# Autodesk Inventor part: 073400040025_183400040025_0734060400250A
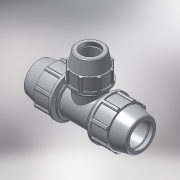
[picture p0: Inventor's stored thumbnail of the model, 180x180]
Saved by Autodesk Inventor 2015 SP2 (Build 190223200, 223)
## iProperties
Created: 2017-02
Part Number: 073400040025_183400040025_0734060400250A
Material: PVC-Piping
Description: PLASSON REDUCING TEE 40-25-40
Document SubType Name: Modeling
Designer: KIM
Mass: 92.6774 g
Surface Area: 199.44 cm^2
Volume: 66.1981 cm^3
Density: 1.4 g/cm^3
Appearance: Smooth - White
Author: Кирилл
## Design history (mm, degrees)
derived "07340.ipt"
feature "Solid1::07340.ipt"
feature "Solid2::07340.ipt"
tag "TaggingFeature1"
body "Solid1"
other parameters: "d4" = 8.54167, "d5" = 28.7, "d7" = 82, "d11" = 3.41667, "d13" = 120 deg, "d15" = 12 deg, "d16" = 71.34, "d18" = 2, "d19" = 35 deg, "d20" = 17.5 deg, "d21" = 76.26, "d23" = 0, "d25" = 360 deg, "d27" = 1.64, "d33" = 0.8, "d42" = 36.9, "d43" = 2.46, "d46" = 1.2, "d67" = 61.5, "d76" = 25, "d77" = 54, "d78" = 12 deg, "d79" = 84, "d80" = 120 deg, "d81" = 37.5, "d82" = 7, "d87" = 2.8, "d89" = 21, "d90" = 25.2, "d96" = 17.08333, "d98" = 50.22, "d99" = 35 deg, "d100" = 17.5 deg, "d102" = 0, "d103" = 1.08, "d107" = 360 deg, "d109" = 0.75, "d112" = 1.25, "d113" = 3.6, "d114" = 0, "d117" = 205, "d118" = 46.98, "d126" = 36, "d127" = 84, "d131" = 3.36, "d132" = 22.5, "d133" = 58, "d135" = 0, "d138" = 4.1, "d143" = 0, "d148" = 40.5, "d168" = 36, "d170" = 0, "d171" = 25, "d173" = 0, "d175" = 0, "d176" = 3.6, "d177" = 0, "E_" = 82, "A_" = 84, "l_" = 84, "E_1" = 54, "l_1" = 58, "d_1" = 25, "H_" = 205
